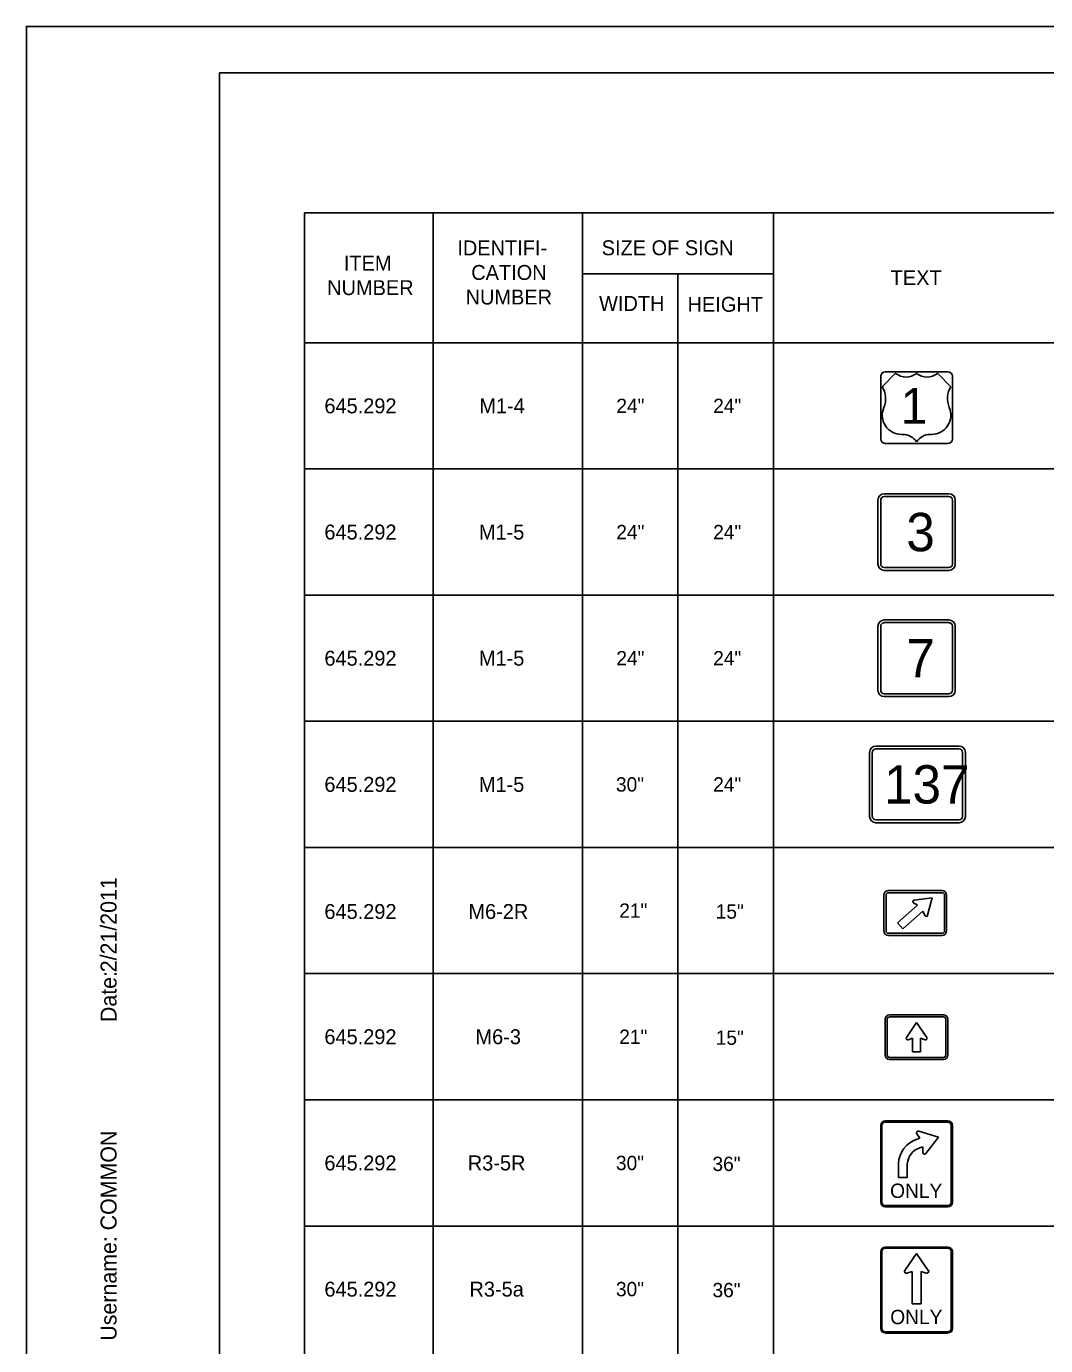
# Model space of a CAD drawing. Extents: x 29767 to 1670682, y 5748 to 339066.
# Drawn here: x 1669832.5 to 1670046, y 338789.4 to 339065.8 of the extents above; entities that cross this region are included whole.
import ezdxf

# ---------------------------------------------------------------- set-up
doc = ezdxf.new("R2010")
doc.units = 0
for name, color, linetype in [('D_Roadway_Pavement', 7, 'Continuous'), ('PDRAIN', 7, 'Continuous'), ('S_Curb_Type_1', 7, 'Continuous'), ('S_Curb_Type_5', 7, 'Continuous'), ('TEXT', 7, 'Continuous')]:
    doc.layers.add(name, color=color, linetype=linetype)

msp = doc.modelspace()

# ---------------------------------------------------------------- linework, layer by layer
at = {"layer": 'D_Roadway_Pavement'}
msp.add_lwpolyline([(1669832.5, 338515.81), (1670682.5, 338515.81), (1670682.5, 339065.81), (1669832.5, 339065.81)], close=True, dxfattribs=at)
at = {"layer": 'PDRAIN'}
for p, q in [((1670014.6, 338993.12), (1670011.79, 338990.31)), ((1670026.17, 338990.31), (1670023.35, 338993.12)), ((1670015.85, 338980.31), (1670016.1, 338980.31)), ((1670021.86, 338980.31), (1670022.1, 338980.31)), ((1670012.22, 338967.9), (1670025.74, 338967.9)), ((1670012.22, 338967.31), (1670025.74, 338967.31)), ((1670010.88, 338953.17), (1670010.88, 338966.56)), ((1670011.46, 338953.17), (1670011.46, 338966.56)), ((1670026.5, 338966.56), (1670026.5, 338953.17)), ((1670027.08, 338966.56), (1670027.08, 338953.17)), ((1670025.74, 338952.42), (1670012.22, 338952.42)), ((1670025.74, 338951.83), (1670012.22, 338951.83)), ((1670010.88, 338926.73), (1670010.88, 338940.12)), ((1670011.46, 338926.73), (1670011.46, 338940.12)), ((1670012.22, 338941.46), (1670025.74, 338941.46)), ((1670012.22, 338940.88), (1670025.74, 338940.88)), ((1670026.5, 338940.12), (1670026.5, 338926.73)), ((1670027.08, 338940.12), (1670027.08, 338926.73)), ((1670025.74, 338925.98), (1670012.22, 338925.98)), ((1670025.74, 338925.4), (1670012.22, 338925.4)), ((1670010.47, 338915.02), (1670027.87, 338915.02)), ((1670009.13, 338900.3), (1670009.13, 338913.69)), ((1670009.71, 338900.3), (1670009.71, 338913.69)), ((1670010.47, 338914.44), (1670027.87, 338914.44)), ((1670028.63, 338913.69), (1670028.63, 338900.3)), ((1670029.21, 338913.69), (1670029.21, 338900.3)), ((1670027.87, 338899.54), (1670010.47, 338899.54)), ((1670027.87, 338898.96), (1670010.47, 338898.96)), ((1670015.01, 338877.97), (1670019.21, 338881.66)), ((1670019.21, 338881.66), (1670018.36, 338882.19)), ((1670018.49, 338882.77), (1670022.23, 338883.21)), ((1670022.23, 338883.21), (1670021.3, 338879.56)), ((1670020.29, 338880.42), (1670016.09, 338876.73)), ((1670020.71, 338879.51), (1670020.29, 338880.42)), ((1670016.09, 338876.73), (1670015.01, 338877.97)), ((1670018.98, 338857.08), (1670016.85, 338853.98)), ((1670021.11, 338853.98), (1670018.98, 338857.08)), ((1670017.19, 338853.5), (1670018.16, 338853.79)), ((1670018.16, 338853.79), (1670018.16, 338850.99)), ((1670019.8, 338850.99), (1670019.8, 338853.79)), ((1670019.8, 338853.79), (1670020.76, 338853.5)), ((1670018.16, 338850.99), (1670019.8, 338850.99)), ((1670011.48, 338819.43), (1670011.48, 338835.55)), ((1670011.73, 338819.43), (1670011.73, 338835.55)), ((1670012.42, 338836.49), (1670025.54, 338836.49)), ((1670012.42, 338836.24), (1670025.54, 338836.24)), ((1670019.44, 338834.36), (1670023.6, 338833.11)), ((1670026.23, 338835.55), (1670026.23, 338819.43)), ((1670026.48, 338835.55), (1670026.48, 338819.43)), ((1670019.69, 338832.84), (1670019.02, 338833.79)), ((1670019.11, 338832.65), (1670019.69, 338832.84)), ((1670023.6, 338833.11), (1670020.95, 338829.67)), ((1670020.27, 338831.06), (1670019.69, 338830.87)), ((1670020.28, 338829.9), (1670020.27, 338831.06)), ((1670015.17, 338824.61), (1670015.17, 338827.49)), ((1670017.04, 338827.49), (1670017.04, 338824.61)), ((1670017.04, 338824.61), (1670015.17, 338824.61)), ((1670025.54, 338818.74), (1670012.42, 338818.74)), ((1670025.54, 338818.49), (1670012.42, 338818.49)), ((1670025.54, 338810.05), (1670012.42, 338810.05)), ((1670025.54, 338809.8), (1670012.42, 338809.8)), ((1670011.48, 338809.12), (1670011.48, 338792.99)), ((1670011.73, 338809.12), (1670011.73, 338792.99)), ((1670018.98, 338808.74), (1670016.51, 338805.16)), ((1670021.44, 338805.16), (1670018.98, 338808.74)), ((1670026.23, 338792.99), (1670026.23, 338809.12)), ((1670026.48, 338792.99), (1670026.48, 338809.12)), ((1670016.94, 338804.59), (1670018.04, 338804.93)), ((1670018.04, 338804.93), (1670018.04, 338798.18)), ((1670019.92, 338798.18), (1670019.92, 338804.93)), ((1670019.92, 338804.93), (1670021.02, 338804.59)), ((1670018.04, 338798.18), (1670019.92, 338798.18)), ((1670012.42, 338792.3), (1670025.54, 338792.3)), ((1670012.42, 338792.05), (1670025.54, 338792.05))]:
    msp.add_line(p, q, dxfattribs=at)
for points in [[(1670011.48, 338979.37), (1670011.48, 338992.5)], [(1670012.42, 338993.43), (1670025.54, 338993.43)], [(1670026.48, 338992.5), (1670026.48, 338979.37)], [(1670025.54, 338978.43), (1670012.42, 338978.43)], [(1670013.09, 338884.73), (1670024.34, 338884.73)], [(1670013.09, 338884.3), (1670024.34, 338884.3)], [(1670012.15, 338876.3), (1670012.15, 338883.8)], [(1670012.58, 338876.3), (1670012.58, 338883.8)], [(1670024.84, 338883.8), (1670024.84, 338876.3)], [(1670025.27, 338883.8), (1670025.27, 338876.3)], [(1670024.34, 338875.79), (1670013.09, 338875.79)], [(1670024.34, 338875.36), (1670013.09, 338875.36)], [(1670012.42, 338850.29), (1670012.42, 338857.79)], [(1670012.85, 338850.29), (1670012.85, 338857.79)], [(1670013.35, 338858.72), (1670024.6, 338858.72)], [(1670013.35, 338858.3), (1670024.6, 338858.3)], [(1670025.11, 338857.79), (1670025.11, 338850.29)], [(1670025.54, 338857.79), (1670025.54, 338850.29)], [(1670024.6, 338849.78), (1670013.35, 338849.78)], [(1670024.6, 338849.35), (1670013.35, 338849.35)]]:
    msp.add_lwpolyline(points, dxfattribs=at)
for centre, radius, start, end in [((1670012.42, 338992.5), 0.937, 90, 180), ((1670016.79, 338995.77), 3.44, 230.4788, 309.5212), ((1670021.17, 338995.77), 3.44, 230.4788, 309.5212), ((1670025.54, 338992.5), 0.937, 360, 90), ((1670007.82, 338987.83), 4.69, 336.7407, 31.9738), ((1670030.14, 338987.83), 4.69, 148.0262, 203.2593), ((1670015.85, 338984.37), 4.06, 156.7407, 270), ((1670022.1, 338984.37), 4.06, 270, 23.2593), ((1670012.42, 338979.37), 0.937, 180, 270), ((1670016.1, 338976.87), 3.44, 33.0557, 90.0481), ((1670021.86, 338976.87), 3.44, 89.9519, 146.9443), ((1670025.54, 338979.37), 0.937, 270, 360), ((1670012.22, 338966.56), 1.34, 90, 180), ((1670012.22, 338966.56), 0.754, 90, 180), ((1670025.74, 338966.56), 1.34, 0, 90), ((1670025.74, 338966.56), 0.754, 0, 90), ((1670012.22, 338953.17), 1.34, 180, 270), ((1670012.22, 338953.17), 0.754, 180, 270), ((1670025.74, 338953.17), 1.34, 270, 0), ((1670025.74, 338953.17), 0.754, 270, 0), ((1670012.22, 338940.12), 1.34, 90, 180), ((1670012.22, 338940.12), 0.754, 90, 180), ((1670025.74, 338940.12), 1.34, 0, 90), ((1670025.74, 338940.12), 0.754, 0, 90), ((1670012.22, 338926.73), 1.34, 180, 270), ((1670012.22, 338926.73), 0.754, 180, 270), ((1670025.74, 338926.73), 1.34, 270, 0), ((1670025.74, 338926.73), 0.754, 270, 0), ((1670010.47, 338913.69), 1.34, 90, 180), ((1670027.87, 338913.69), 1.34, 0, 90), ((1670010.47, 338913.69), 0.754, 90, 180), ((1670027.87, 338913.69), 0.754, 0, 90), ((1670010.47, 338900.3), 1.34, 180, 270), ((1670010.47, 338900.3), 0.754, 180, 270), ((1670027.87, 338900.3), 1.34, 270, 0), ((1670027.87, 338900.3), 0.754, 270, 0), ((1670013.09, 338883.8), 0.937, 90, 180), ((1670013.09, 338883.8), 0.508, 90, 180), ((1670024.34, 338883.8), 0.937, 0, 90), ((1670024.34, 338883.8), 0.508, 0, 90), ((1670018.52, 338882.46), 0.312, 96.7689, 237.9013), ((1670021, 338879.64), 0.312, 204.6127, 345.7451), ((1670013.09, 338876.3), 0.937, 180, 270), ((1670013.09, 338876.3), 0.508, 180, 270), ((1670024.34, 338876.3), 0.937, 270, 0), ((1670024.34, 338876.3), 0.508, 270, 0), ((1670013.35, 338857.79), 0.937, 90, 180), ((1670013.35, 338857.79), 0.508, 90, 180), ((1670024.6, 338857.79), 0.937, 0, 90), ((1670024.6, 338857.79), 0.508, 0, 90), ((1670017.1, 338853.8), 0.312, 145.5119, 286.6443), ((1670020.85, 338853.8), 0.312, 253.3557, 34.4881), ((1670013.35, 338850.29), 0.937, 180, 270), ((1670013.35, 338850.29), 0.508, 180, 270), ((1670024.6, 338850.29), 0.937, 270, 0), ((1670024.6, 338850.29), 0.508, 270, 0), ((1670012.42, 338835.55), 0.938, 90, 180), ((1670012.42, 338835.55), 0.687, 90, 180), ((1670019.33, 338834), 0.375, 73.3254, 215.2026), ((1670025.54, 338835.55), 0.938, 0, 90), ((1670025.54, 338835.55), 0.687, 0, 90), ((1670020.85, 338827.24), 5.69, 107.8394, 176.9831), ((1670020.85, 338827.24), 3.81, 107.8395, 176.9831), ((1670020.65, 338829.9), 0.375, 180.4774, 322.3546), ((1670012.42, 338819.43), 0.938, 180, 270), ((1670012.42, 338819.43), 0.687, 180, 270), ((1670025.54, 338819.43), 0.938, 270, 0), ((1670025.54, 338819.43), 0.687, 270, 0), ((1670012.42, 338809.12), 0.938, 90, 180), ((1670012.42, 338809.12), 0.687, 90, 180), ((1670025.54, 338809.12), 0.938, 0, 90), ((1670025.54, 338809.12), 0.687, 0, 90), ((1670016.82, 338804.94), 0.375, 145.4854, 287.3626), ((1670021.14, 338804.94), 0.375, 252.6374, 34.5146), ((1670012.42, 338792.99), 0.938, 180, 270), ((1670012.42, 338792.99), 0.687, 180, 270), ((1670025.54, 338792.99), 0.938, 270, 0), ((1670025.54, 338792.99), 0.687, 270, 0)]:
    msp.add_arc(centre, radius, start, end, dxfattribs=at)
at = {"layer": 'S_Curb_Type_1'}
for p, q in [((1670374.95, 339026.77), (1669890.74, 339026.77)), ((1669890.74, 339026.77), (1669890.74, 338554.38)), ((1669917.74, 339026.77), (1669917.74, 338554.38)), ((1669948.98, 338554.38), (1669948.98, 339026.77)), ((1669988.98, 338554.38), (1669988.98, 339026.77)), ((1669948.98, 339013.95), (1669988.98, 339013.95)), ((1669968.98, 338554.38), (1669968.98, 339013.95)), ((1670374.95, 338999.52), (1669890.74, 338999.52)), ((1670374.95, 338973.08), (1669890.74, 338973.08)), ((1670374.95, 338946.65), (1669890.74, 338946.65)), ((1670374.95, 338920.21), (1669890.74, 338920.21)), ((1670374.95, 338893.77), (1669890.74, 338893.77)), ((1670374.95, 338867.34), (1669890.74, 338867.34)), ((1670374.95, 338840.9), (1669890.74, 338840.9)), ((1670374.95, 338814.46), (1669890.74, 338814.46))]:
    msp.add_line(p, q, dxfattribs=at)
at = {"layer": 'TEXT'}
for p, q in [((1670672.96, 339056.11), (1669872.96, 339056.11)), ((1669872.96, 339056.11), (1669872.96, 338531.11))]:
    msp.add_line(p, q, dxfattribs=at)

# ---------------------------------------------------------------- texts
at = {"layer": 'PDRAIN'}
for s, height, rotation, p in [('1', 7.5, 360, (1670015.67, 338982.55)), ('3', 8.03, 0, (1670016.83, 338955.85)), ('7', 8.03, 0, (1670016.83, 338929.41)), ('137', 8.033, 0, (1670012.15, 338902.98)), ('ONLY', 3, 0, (1670013.44, 338820.35)), ('ONLY', 3, 0, (1670013.47, 338793.91))]:
    msp.add_text(s, height=height, rotation=rotation, dxfattribs=at).set_placement(p)
at = {"layer": 'S_Curb_Type_5'}
for s, height, p in [('IDENTIFI-', 3.125, (1669922.78, 339017.83)), ('SIZE OF SIGN', 3.125, (1669953.02, 339017.86)), ('ITEM', 3.125, (1669899, 339014.65)), ('CATION', 3.125, (1669925.69, 339012.69)), ('TEXT', 3.125, (1670013.55, 339011.6)), ('NUMBER', 3.125, (1669895.51, 339009.51)), ('NUMBER', 3.125, (1669924.51, 339007.54)), ('WIDTH', 3.125, (1669952.47, 339006.2)), ('HEIGHT', 3.125, (1669971.01, 339006.01)), ('645.292', 3.125, (1669894.93, 338984.74)), ('M1-4', 3.125, (1669927.38, 338984.74)), ('24"', 3, (1669956.08, 338984.8)), ('24"', 3, (1669976.37, 338984.8)), ('645.292', 3.125, (1669894.93, 338958.3)), ('M1-5', 3.125, (1669927.29, 338958.3)), ('24"', 3, (1669956.08, 338958.36)), ('24"', 3, (1669976.37, 338958.36)), ('645.292', 3.125, (1669894.93, 338931.87)), ('M1-5', 3.125, (1669927.29, 338931.87)), ('24"', 3, (1669956.08, 338931.93)), ('24"', 3, (1669976.37, 338931.93)), ('645.292', 3.125, (1669894.93, 338905.43)), ('M1-5', 3.125, (1669927.29, 338905.43)), ('30"', 3, (1669956, 338905.49)), ('24"', 3, (1669976.37, 338905.49)), ('645.292', 3.125, (1669894.93, 338878.8)), ('M6-2R', 3.125, (1669925.1, 338878.8)), ('21"', 3, (1669956.69, 338879.05)), ('15"', 3, (1669976.9, 338878.86)), ('645.292', 3.125, (1669894.93, 338852.56)), ('M6-3', 3.125, (1669926.58, 338852.56)), ('21"', 3, (1669956.69, 338852.62)), ('15"', 3, (1669976.9, 338852.43)), ('645.292', 3.125, (1669894.93, 338826.12)), ('R3-5R', 3.125, (1669924.97, 338826.12)), ('30"', 3, (1669956, 338826.18)), ('36"', 3, (1669976.22, 338825.99)), ('645.292', 3.125, (1669894.93, 338799.68)), ('R3-5a', 3.125, (1669925.32, 338799.68)), ('30"', 3, (1669956, 338799.75)), ('36"', 3, (1669976.22, 338799.55))]:
    msp.add_text(s, height=height, dxfattribs=at).set_placement(p)
at = {"layer": 'TEXT'}
for s, p in [('2/21/2011', (1669851.39, 338867.63)), ('Date:', (1669851.39, 338857.19)), ('COMMON', (1669851.39, 338813.56)), ('Username:', (1669851.39, 338790.44))]:
    msp.add_text(s, height=3.348, rotation=90, dxfattribs=at).set_placement(p)

doc.saveas('drawing.dxf')
